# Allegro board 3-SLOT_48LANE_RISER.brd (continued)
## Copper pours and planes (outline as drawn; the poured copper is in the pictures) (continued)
P1V8_AGND on TOP (solid shape): 45.97,108.19 45.97,104.07 45.95,104.05 45.74,104.05 45.7,104.09 45.7,104.46 45.69,104.53 45.67,104.61 45.67,104.89 45.64,104.91 45.52,104.91 45.52,104.91 44.63,104.91 44.58,104.96 44.58,107.3 44.67,107.4 45.61,107.4 45.67,107.45 45.67,107.7 45.69,107.78 45.7,107.86 45.7,108.14 45.72,108.19 45.78,108.21 45.95,108.21
P1V8_AGND on BOTTOM (solid shape): 45.57,106.16 45.57,106.03 45.56,106 45.54,105.98 45.29,105.72 44.7,105.72 44.6,105.62 44.6,104.43 44.58,104.37 44.53,104.35 44.33,104.3 44.15,104.2 43.58,104.2 43.46,104.32 43.46,105.29 43.3,105.44 43.18,105.44 43,105.62 43,105.95 43.2,106.15 44.45,106.15 44.65,106.36 45.37,106.36
P3V3 on TOP (solid shape): 307.94,54.3 307.94,53.04 307.86,52.96 307.72,52.96 307.72,52.95 306.18,52.95 306.14,52.99 306.14,54.36 306.18,54.39 307.85,54.39
P3V3 on TOP (solid shape): 288.77,35.94 288.77,34.72 287.85,33.8 287.85,33.32 287.85,33.26 287.85,33.2 287.85,32.77 288.52,32.11 288.52,31.43 288.62,31.33 288.62,30.86 288.49,30.73 284.64,30.73 284.58,30.73 284.57,30.75 282.77,30.75 282.65,30.86 282.65,31.37 285.67,34.39 285.7,34.4 285.73,34.41 285.85,34.4 285.98,34.42 286.46,34.42 286.72,34.67 286.72,35.81 287.1,36.2 288.52,36.2
P3V3 on TOP (solid shape): 288.88,76.58 288.88,76.12 288.87,76.11 288.85,75.89 288.87,75.68 288.88,75.67 288.88,74.93 288.82,74.87 288.79,74.87 287.88,74.12 288.36,73.04 288.37,73.03 288.88,72.52 288.88,72.26 288.88,71.5 288.75,71.37 282.91,71.37 282.78,71.5 282.78,72.01 285.81,75.04 285.84,75.04 286.53,75.41 286.63,76.18 286.63,76.22 286.65,76.26 287.1,76.71 288.75,76.71
P3V3 on BOTTOM (solid shape): 279.1,114.3 279.1,112.52 279.22,112.39 279.6,112.39 279.99,112.01 279.99,108.46 281.51,106.93 282.14,106.93 282.4,106.68 282.4,98.55 282.27,98.42 276.68,98.42 276.43,98.68 276.43,114.3 276.81,114.68 278.72,114.68
P3V3 on VCC (solid shape): outline of 11865 points within 55.32,5.69 321.03,92.71
P3V3 on IN2 (solid shape): outline of 6449 points within 188.16,44.32 311.1,116.2
P3V3_AGND on TOP (solid shape): 298.1,106.25 298.1,105.49 298.2,105.38 299.6,105.38 299.7,105.49 299.79,105.49 299.88,105.39 299.88,105.06 299.32,104.51 299.32,103.67 299.27,103.62 298.52,103.62 298.46,103.68 298.46,104.21 298.27,104.39 297.13,104.39 296.62,104.9 296.62,106.32 296.85,106.55 297.79,106.55
P3V3_BUF_VDDA on TOP (solid shape): 298.97,56.49 298.97,55.81 298.37,55.22 294.74,55.22 294.65,55.3 294.65,56.26 294.77,56.37 296.43,56.37 296.77,56.03 298.19,56.03 298.68,56.52 298.93,56.52
P3V3_BUF_VDDR on TOP (solid shape): 300.54,54.48 300.54,53.62 300.55,53.62 300.55,53.56 300.55,53.56 300.55,53.48 300.79,53.25 300.79,51.49 300.74,51.44 300.12,51.44 299.92,51.65 299.92,54.47 300,54.56 300.47,54.56
P3V3_CLK_BUF_VDD on TOP (solid shape): 304.74,56.8 304.74,56.1 305.1,55.73 305.1,54.81 305.43,54.48 305.43,52.45 305.26,52.28 304.39,52.28 304.25,52.42 304.25,56.21 304.21,56.26 304.21,56.82 304.27,56.87 304.67,56.87
P3V3_CLK_BUF_VDD on BOTTOM (solid shape): outline of 1205 points within 294.16,49.96 307.04,65.08
P3V3_MB on TOP (solid shape): outline of 227 points within 284.81,1.54 291.29,22.86
P3V3_MB on BOTTOM (solid shape): outline of 599 points within 285.98,1.43 292.18,21.94
P3V3_MB on VCC (solid shape): 291.54,21.61 291.54,19.03 290.65,18.14 290.65,14.25 291.42,13.48 291.42,11.92 291.16,11.66 291.16,5.69 286.3,5.69 286.3,6.76 286.44,7.06 286.3,7.36 286.3,7.45 286.01,8.47 285.25,9.19 285.25,9.2 285.19,9.25 285.19,15.21 285.34,15.39 285.46,15.6 285.68,15.6 285.79,16.19 285.68,16.78 285.46,16.78 285.34,16.98 285.19,17.16 285.19,21.61 285.68,22.1 291.06,22.1
P3V3_STBY_MB on TOP (solid shape): 284.41,22.07 284.41,21.49 285.88,20.02 286.2,20.02 286.21,20.01 287.1,20.01 287.48,19.63 287.48,19.05 287.1,18.67 285.83,18.67 283.41,21.08 283.41,21.47 283.42,22.1 283.52,22.2 284.28,22.2
P3V3_STBY_MB on TOP (solid shape): 286.84,83.46 286.93,83.46 287.22,83.46 287.33,83.36 287.33,82.63 287.52,82.44 287.52,81.35 287.52,81.34 287.52,79.79 287.35,79.63 286.36,79.63 286.16,79.83 286.16,82.47 286.41,82.73 286.41,83.41 286.46,83.46 286.76,83.46
P3V3_STBY_MB on TOP (solid shape): 286.84,42.94 286.93,42.95 287.2,42.95 287.31,42.84 287.31,41.9 287.48,41.73 287.48,39.37 287.22,39.12 286.36,39.12 286.16,39.32 286.16,41.73 286.34,41.91 286.34,42.17 286.34,42.88 286.41,42.95 286.76,42.95
P3V3_STBY_MB on BOTTOM (solid shape): 285.57,13.97 285.57,12.57 285.45,12.45 284.05,12.45 283.92,12.57 283.92,13.08 283.29,13.72 283.29,14.22 283.54,14.48 285.07,14.48
P3V3_STBY_MB on IN1 (solid shape): outline of 12737 points within 268.3,10.49 317.96,88.62
P12V on TOP (solid shape): 55.41,37.45 55.41,35.83 55.31,35.73 54.9,35.73 54.85,35.68 54.85,34.94 54.77,34.86 53.32,34.86 52.94,35.24 52.94,37.28 53.28,37.61 55.25,37.61
P12V on TOP (solid shape): 297.28,41.45 297.28,31.6 296.7,31.01 295.1,31.01 294.84,30.76 293.35,30.76 293.27,30.84 293.27,32.26 293.73,32.72 293.73,34.34 293.66,34.4 296.68,34.4 296.68,36.11 294.98,36.11 294.98,34.4 293.66,34.4 293.22,34.85 293.22,38.63 293.96,39.37 293.96,43.69 294.08,43.81 294.92,43.81
P12V on TOP (solid shape): 297.82,82.75 297.82,72.11 297.36,71.65 295.1,71.65 294.84,71.4 293.35,71.4 293.27,71.48 293.27,72.9 293.73,73.36 293.73,74.98 293.66,75.04 296.68,75.04 296.68,76.75 294.98,76.75 294.98,75.04 293.66,75.04 293.22,75.49 293.22,79.27 293.96,80.01 293.96,84.33 294.08,84.45 296.11,84.45
P12V on TOP (solid shape): outline of 648 points within 1.45,85.59 45.54,115.44
P12V on BOTTOM (solid shape): 288.33,113.59 288.33,112.96 288.11,112.74 288.11,111 287.99,110.87 285.22,110.87 284.84,111.25 284.84,113.41 285.22,113.79 288.12,113.79
P12V on VCC (solid shape): outline of 4277 points within 1.02,31.24 321.03,117.23
P12V_MB on TOP (solid shape): 298.78,19.94 301.83,19.94 302.08,19.68 302.08,16.13 301.96,16 299.8,16 296.11,12.32 296.11,10.03 294.77,8.69 294.77,6.22 295.19,5.8 295.19,1.51 295.15,1.47 294.52,1.47 294.49,1.48 294.47,1.5 294.45,1.51 294.45,1.55 294.45,5.64 294.21,5.64 294.21,1.55 294.2,1.51 294.19,1.5 294.17,1.48 294.13,1.47 293.55,1.47 293.51,1.48 293.5,1.5 293.48,1.51 293.47,1.55 293.47,5.89 292.86,6.5 292.86,9.19 293.83,10.17 293.96,10.17 293.96,12.01 294.01,12.06 294.01,13.46 293.39,14.08 296.68,14.08 296.68,15.79 294.98,15.79 294.98,14.08 293.39,14.08 292.94,14.54 292.94,14.54 292.94,18.03 293.83,18.92 293.83,19.81 294.46,20.45 298.27,20.45
P12V_MB on BOTTOM (solid shape): outline of 189 points within 292.86,1.43 300.94,20.07
P12V_MB on VCC (solid shape): 303.1,21.74 303.1,10.01 302.51,9.42 301.1,9.42 300.81,9.55 300.53,9.42 297.74,9.42 296.63,9.14 295.8,8.35 295.54,8.13 295.55,7.8 295.48,7.47 295.45,7.14 295.45,5.69 291.67,5.69 291.67,11.45 291.92,11.71 291.92,13.69 291.16,14.46 291.16,17.93 292.05,18.82 292.05,21.61 292.92,22.48 302.36,22.48
P12V_PSU on TOP (solid shape): 10.96,88.94 11.54,88.36 12.36,88.39 15.06,88.39 15.32,88.14 15.32,87 15.19,86.87 14.22,86.87 14.22,86.79 14.17,86.74 14.17,85.93 13.72,85.47 8.59,85.47 7.7,86.36 7.7,89.66 8.21,90.17 9.73,90.17
P12V_PSU on IN2 (solid shape): 11.38,88.39 12.52,88.39 13.3,87.62 13.3,85.86 13.16,85.72 9.6,85.72 7.7,87.63 7.7,89.53 8.33,90.17 9.6,90.17
VR_P0V9_PVIN on TOP (solid shape): outline of 88 points within 56.17,34.81 67.25,41.82
VR_P0V9_PVIN on BOTTOM (solid shape): 64.93,42.25 64.93,40.81 66.7,39.04 66.7,37.16 66.3,36.76 63.25,36.76 62.82,36.32 57.61,36.32 57.35,36.58 57.35,37.52 64.32,37.52 64.33,37.46 64.34,37.41 64.36,37.35 64.39,37.31 64.42,37.26 64.46,37.22 64.51,37.19 64.56,37.16 64.61,37.15 64.66,37.14 64.72,37.13 64.78,37.14 64.83,37.15 64.88,37.18 64.93,37.21 64.97,37.24 65.01,37.28 65.04,37.33 65.06,37.38 65.08,37.43 65.09,37.49 65.09,37.54 65.08,37.6 65.06,37.65 65.04,37.7 65.01,37.75 64.97,37.79 64.93,37.83 64.88,37.86 64.83,37.88 64.78,37.89 64.72,37.9 64.66,37.9 64.61,37.89 64.56,37.87 64.51,37.84 64.46,37.81 64.42,37.77 64.39,37.73 64.36,37.68 64.34,37.63 64.33,37.57 64.32,37.52 57.35,37.52 57.35,37.97 57.48,38.1 61.46,38.1 62.14,38.78 62.14,42.89 62.56,43.31 63.87,43.31
VR_P0V9_SW on TOP (solid shape): 62.69,45.59 62.69,44.58 62.9,44.37 66.69,44.37 66.74,44.34 66.76,44.29 66.76,42.26 66.74,42.23 63.74,42.23 63.74,42.23 63.45,42.23 63.35,42.12 63.35,41.84 62.7,41.19 62.5,40.99 58.43,40.99 58.36,41.06 58.36,45.58 58.5,45.72 62.56,45.72
VR_P1V8_PVIN on TOP (solid shape): 51.13,111.63 51.13,109.09 50.88,108.84 49.94,108.84 48.08,106.98 46.38,106.98 46.26,107.11 46.26,110.49 46.26,110.87 48.17,110.87 48.17,110.2 48.17,110.18 48.18,110.12 48.19,110.06 48.22,110.01 48.24,109.97 48.24,109.85 48.35,109.85 48.39,109.82 48.44,109.8 48.5,109.78 48.56,109.76 48.62,109.76 48.68,109.76 48.74,109.78 48.79,109.8 48.85,109.82 48.88,109.85 49,109.85 49,109.97 49.02,110.01 49.04,110.06 49.05,110.12 49.06,110.18 49.06,110.2 49.06,110.87 49.06,110.9 49.05,110.96 49.04,111.02 49.01,111.08 48.98,111.13 48.94,111.18 48.9,111.22 48.85,111.25 48.79,111.28 48.74,111.3 48.68,111.31 48.62,111.32 48.56,111.31 48.5,111.3 48.44,111.28 48.39,111.25 48.34,111.22 48.29,111.18 48.25,111.13 48.22,111.08 48.2,111.02 48.18,110.96 48.17,110.9 48.17,110.87 46.26,110.87 46.26,112.6 46.31,112.65 50.12,112.65
VR_P1V8_PVIN on BOTTOM (solid shape): 48.1,110.52 48.11,110.52 48.11,109.96 48.46,109.6 48.46,108.58 48.21,108.33 47.25,108.33 46.56,109.02 46.56,110.75 46.71,110.9 47.72,110.9
VR_P1V8_SW on TOP (solid shape): 50.53,106.68 51.03,106.68 51.41,106.3 51.41,102.23 51.28,102.11 49.25,102.11 49,102.36 49,104.78 48.57,105.21 46.29,105.21 46.24,105.26 46.24,106.6 46.33,106.69 50.52,106.69
VR_P3V3_PVIN on TOP (solid shape): 294.08,111.89 294.08,106.68 293.83,106.43 292.43,106.43 292.18,106.68 292.18,109.98 291.03,111.12 290.02,111.12 289.76,111.38 289.76,112.14 290.02,112.39 293.57,112.39
VR_P3V3_PVIN on BOTTOM (solid shape): 298.65,112.01 298.65,109.73 298.27,109.35 296.24,109.35 295.55,108.65 295.55,106.75 295.48,106.68 292.94,106.68 292.3,107.31 292.3,109.47 291.67,110.11 289,110.11 288.75,110.36 288.75,112.27 289,112.52 298.15,112.52
VR_P3V3_SW on BOTTOM (solid shape): 292.51,106.38 293.07,106.38 293.17,106.27 295.79,106.27 295.79,104.67 295.76,104.65 292.69,104.65 291.66,103.62 291.66,103.24 291.03,102.62 287.61,102.62 287.41,102.81 287.41,107.4 287.67,107.66 291.23,107.66

Small or netless copper shapes (teardrops, artwork), in the pictures only: 83 on TOP, 3 on BOTTOM, 1 on GND, 2 on IN1, 2 on VCC, 2 on VCC1, 2 on IN2, 1 on GND1

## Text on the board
Ref Des/Silkscreen Bottom: Sliver_1 | (P0 PCIe 3AB) | Sliver_2 | (P0 PCIe 3CD) | PWR_Conn
User.Comments: 2018/08/13 | Moxlie_3slot_riser | PCB-3RSMOXL8-P2
Ref Des/Silkscreen Top: C | D | B | J1 | Riser Slot1 (P1 PCIe 1ABCD) | J3 | Riser Slot3 (PLX PCIe P16) | J2 | Riser Slot2 (PLX PCIe P8) | PCB-3RSMOXL8-P2 REV:P2
User.34: FIGURE | SIZE | 10.0 | 16.0 | 22.0 | 24.0 | 28.0 | 41.0 | 44.0 | 221.0 | 47.0 | 95.0 | 119.0 | 158.0 | DRILL CHART: TOP to BOTTOM | ALL UNITS ARE IN MILS | TOLERANCE | +0.0/-10.0 | +3.0/-3.0 | +3.0/-5.0 | +3.0/-0.0 | +4.0/-0.0 | +2.0/-2.0 | PLATED | NON-PLATED | QTY | 406 | 1 | 123 | 2488 | 10 | 2 | 60 | 30 | 4 | 492 | 48 | 11 | 6
